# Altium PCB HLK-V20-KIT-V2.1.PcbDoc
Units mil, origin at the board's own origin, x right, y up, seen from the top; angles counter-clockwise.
Board outline 1181.1 x 1102.36 mil, 2 copper layers (Top Layer, Bottom Layer); 18 components, 58 nets, 96 pads, 45 vias.
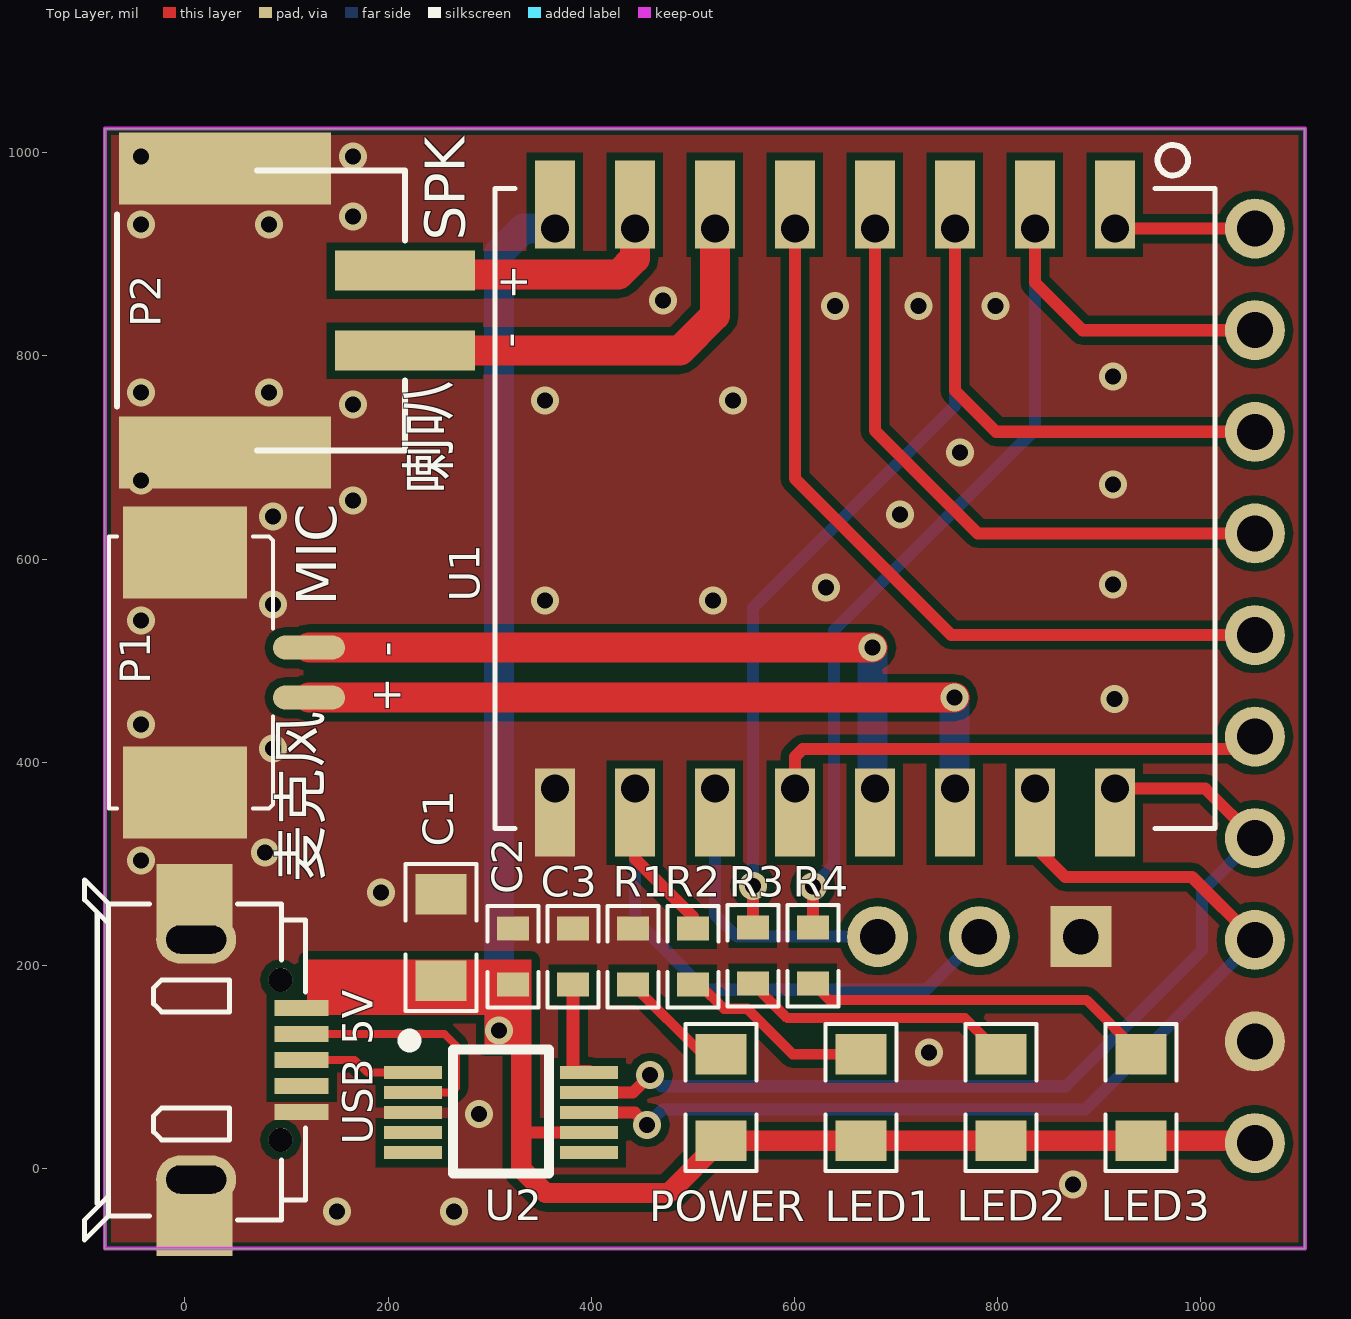
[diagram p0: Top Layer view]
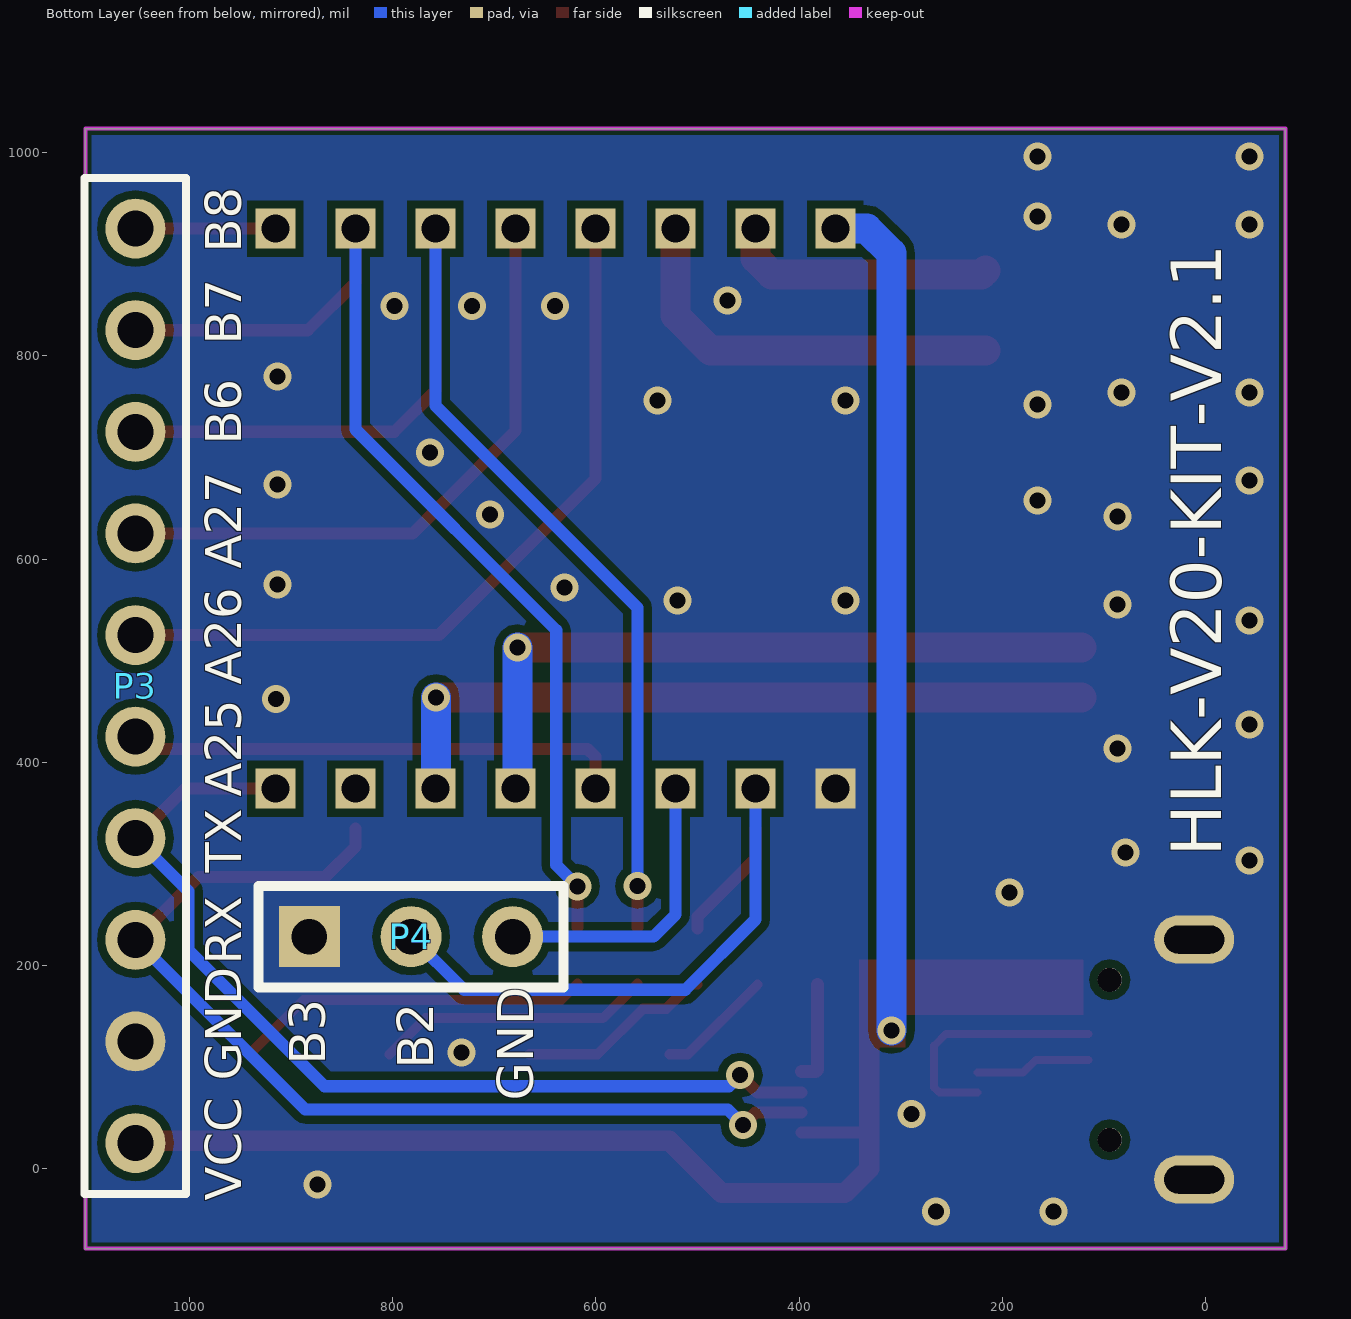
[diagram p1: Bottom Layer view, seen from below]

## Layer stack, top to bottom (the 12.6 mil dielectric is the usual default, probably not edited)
Top Layer: signal copper 1.4
Dielectric: dielectric 12.6, FR-4, Dk 4.8
Bottom Layer: signal copper 1.4

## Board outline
-78.74,-78.74 -78.74,1023.62 1102.36,1023.62 1102.36,-78.74

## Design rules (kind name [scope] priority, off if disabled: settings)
Clearance Clearance_1 [OnLayer('Keep-Out Layer')] p1: gap=3.94
Clearance [All] p2: gap=7.87
PlaneConnect [All] p1: planeconnectstyle=Direct reliefexpansion=20 reliefentries=4 reliefconductorwidth=10 reliefairgap=10
PolygonConnect [All] p1: connectstyle=Direct reliefconductorwidth=10 reliefentries=4 polygonreliefangle="90 Angle"
RoutingVias [All] p1: holewidth=15.75 width=27.56 viastyle="Through Hole" minholewidth=15.75 minwidth=27.56 maxholewidth=15.75 maxwidth=27.56
SilkscreenOverComponentPads SilkToSolderMaskClearance [IsPad] p1: minsilkscreentomaskgap=10
SolderMaskExpansion [All] p1: expansion=4
TestPointUsage FabricationTestPointUsage [All] p1: valid=0 allowmultiple=FALSE
Testpoint FabricationTestpoint [(IsPad And (OnTopLayer Or OnBottomLayer))] p1: side=3 testpointundercomponent=TRUE minsize=40 maxsize=100 preferedsize=60 minholesize=0 maxholesize=40 preferedholesize=32 testpointgrid=1 style=297 order=0123456789
Width [All] p1: maxlimit=196.85 minlimit=7.09 preferedwidth=10
22 further rules are at their usual default settings.

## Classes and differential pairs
component class HLK-V01-KIT-V1.0: C1 C2 LED1 LED2 LED3 P1 POWER R1 R2 R3 R4 R10 R11 "USB 5V"

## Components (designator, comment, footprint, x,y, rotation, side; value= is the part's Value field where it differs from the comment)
C1 "4.7UF" 0805R 251.97,270.04 r270 top
C2 "0.1UF" 0603 322.83,208.66 r270 top
C3 "0.1UF" 0603 381.89,208.66 r270 top
LED1 "LED2" 0805R 665.35,27.56 r90 top
LED2 "LED2" 0805R 803.15,27.56 r90 top
LED3 "LED3" 0805R 940.94,27.56 r90 top
P1 "1.25*2_SMT" 1.25-2P 122.05,488.19 r90 top locked
P2 "2.0*2_SMT" PH2.0-2P 216.54,805.12 r90 top
P3 "2.54*10" HDR1X10 1053.15,925.2 r270 bottom locked
P4 "2.54*3" SIP3 881.89,228.35 r180 bottom
POWER "LED" 0805R 527.56,27.56 r90 top
R1 "1K" 0603 440.94,208.66 r90 top
R2 "1K" 0603 500,208.66 r90 top
R3 "1K" 0603 559.06,209.66 r90 top (schematic designator R4)
R4 "1K" 0603 618.11,209.66 r90 top (schematic designator R10)
U1 "Comment" HLK-V20 915.35,964.57 r270 top
U2 "CH340E" MSOP-10 311.02,55.12 r270 top (schematic designator U1)
"USB 5V" "USB" usb 7.87,106.3 r270 top locked (schematic designator USB1)

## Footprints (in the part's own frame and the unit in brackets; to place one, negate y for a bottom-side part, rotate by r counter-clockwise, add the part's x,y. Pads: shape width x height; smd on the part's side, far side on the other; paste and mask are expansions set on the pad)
1.25-2P [mm]
  oval 0.6x1.8 smd: 1(0.625,0) 2(-0.625,0)
  rect 2.3x3.1 smd: 3(-3,3.1) 4(3,3.1)
  silkscreen extent -3.4,0.9 3.4,5
0603 [mm]
  rect 0.6x0.8 smd: 1(-0.7,0) 2(0.7,0)
  silkscreen extent -1.27,-0.64 1.27,0.64
0805R [mil]
  rect 40x50 smd: 1(0,0) 2(85,0)
  silkscreen extent -30,-35 115,35, body extent 4,-25 83,25, height 22
HDR1X10 [mm]
  round 1.5 hole 0.9: 1(0,0) 2(2.54,0) 3(5.08,0) 4(7.62,0) 5(10.16,0) 6(12.7,0) 7(15.24,0) 8(17.78,0) 9(20.32,0) 10(22.86,0)
  silkscreen extent -1.27,-1.27 24.13,1.27
HLK-V20 [mm]
  rect 1.4x1 smd: 1(0,0) 2(0,-2) 3(0,-4) 4(0,-6) 5(0,-8) 6(0,-10) 7(0,-12) 8(0,-14) 9(16,-14) 10(16,-12) 11(16,-10) 12(16,-8) 13(16,-6) 14(16,-4) 15(16,-2) 16(16,0)
  rect 1x1 hole 0.7: 1(1,0) 2(1,-2) 3(1,-4) 4(1,-6) 5(1,-8) 6(1,-10) 7(1,-12) 8(1,-14) 9(15,-14) 10(15,-12) 11(15,-10) 12(15,-8) 13(15,-6) 14(15,-4) 15(15,-2) 16(15,0)
  silkscreen extent -1.09,-15.5 16,2.5
MSOP-10 [mm]
  rect 0.33x1.45 smd: 1(-1,-2.2) 2(-0.5,-2.2) 3(0,-2.2) 4(0.5,-2.2) 5(1,-2.2) 6(1,2.2) 7(0.5,2.2) 8(0,2.2) 9(-0.5,2.2) 10(-1,2.2)
  silkscreen extent -1.95,-2.44 1.53,1.2
PH2.0-2P [mm]
  rect 1x3.5 smd: 1(0,0) 2(2,0)
  rect 1.8x5.3 smd: 3(4.55,4.5) 4(-2.55,4.5)
  silkscreen extent -2.5,0 4.5,7.2
SIP3 [mil]
  rect 60x60 hole 35: 1(0,0)
  round 60 hole 35: 2(100,0) 3(200,0)
  silkscreen extent -50,-50 250,50
usb [mm]
  oval 1.2x2 hole 0.7 slot 1.5 at 90 deg: 1(-3.028,0.081) 1(2.972,0.081)
  rect 0.4x1.35 smd: 1(1.28,2.719) 2(0.63,2.719) 3(-0.02,2.719) 4(-0.67,2.719) 5(-1.32,2.719)
  round 0.6 hole 0.6: 6(1.98,2.194) 9(-2.02,2.194)
  rect 1.8x1.9 smd: 7(3.98,0.044) 8(-4.02,0.044)
  silkscreen extent -4.52,-2.71 4.48,2.82

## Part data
C1 C2 C3: library part CAP, "Capacitor"
LED1 LED2 LED3: library part LED
P1: library part Component_1
R1 R2 R3 R4: library part RES1
"USB 5V": library part USB-B

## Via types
v1: diameter 27.56, hole 15.75, Top Layer to Bottom Layer, tented both sides, 45 vias

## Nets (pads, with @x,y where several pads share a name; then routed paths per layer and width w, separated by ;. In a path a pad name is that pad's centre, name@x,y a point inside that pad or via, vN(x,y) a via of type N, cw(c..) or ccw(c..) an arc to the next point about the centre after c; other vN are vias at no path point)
3.3V: 
5V: "USB 5V.5" C1.2 C2.2 LED1.1 LED2.1 LED3.1 P3.10 POWER.1 U1.8 U2.7 | length 1943.7
  Top Layer w10: 333,54 333,164
  Top Layer w12: 333,35.43 U2.7
  Top Layer w20: C2.2 331,172.94 331,0 355,-24 476,-24 POWER.1 LED1.1 LED2.1 LED3.1 1050.79,27.56 P3.10
  Bottom Layer w29.53: v1(309,136) 309,901 333.2,925.2 U1.8@364.17,925.2
ACE_N: 
ACE_P: 
CTS: U2.5
DM: "USB 5V.4" U2.2 | length 242.7
  Top Layer w7.87: 114.91,132.68 255.32,132.68 267,121 267,80 261.8,74.8 U2.2
DP: "USB 5V.3" U2.1 | length 114.7
  Top Layer w7.87: 114.91,107.09 166.91,107.09 179.51,94.49 U2.1
GND: "USB 5V.1" "USB 5V.7" "USB 5V.8" C1.1 C2.1 C3.1 P1.3 P1.4 P2.3 P2.4 P3.9 P4.1 R1.2 U1.9 U2.3
  other v1: 149.61,-42.22 265,-42 874.02,-15.75 289.32,54 732.28,114.17 192.91,271.65 -43.31,303.15 78.74,311.02 86.61,413.39 -43.31,437.01 915,462 -43.31,539.37 86.61,555.12 354.33,559.06 519.68,559.06 631,572 913.39,574.8 86.61,641.73 704,644 165.35,657.48 913.39,673.23 -43.31,677.17 763,705 165.35,751.97 354.33,755.91 539.37,755.91 -43.31,763.78 82.68,763.78 913.39,779.53 640,849 722,849 798,849 470.47,854.33 -43.31,929.13 82.68,929.13 165.35,937.01 -43.31,996.06 165.35,996.06
IO9: 
IO10: 
IO11: 
MIC0_N: 
MIC0_P: 
MIC+: P1.2 U1.14 | length 725.1
  Top Layer w29.53: P1.2 v1(757.29,463.58)
  Bottom Layer w29.53: v1(757.29,463.58) 757.29,374.6 U1.14@757.87,374.02
MIC-: P1.1 U1.13 | length 694.6
  Top Layer w29.53: P1.1 v1(676.93,512.8)
  Bottom Layer w29.53: v1(676.93,512.8) 676.93,376.22 U1.13@679.13,374.02
NetC3_2: C3.2 U2.10 | length 100.3
  Top Layer w12.99: C3.2 381.89,97.11 383.33,95.67 U2.10@397.64,95.67
NetCHRX_1: 
NetCHTX_1: 
NetLED1_2: LED1.2 R2.1 | length 193.7
  Top Layer w10: R2.1 506.9,181.1 530.59,157.41 553.45,157.41 598.31,112.56 LED1.2
NetLED2_2: LED2.2 R3.1 | length 272.9
  Top Layer w10: R3.1 593.03,148.13 767.58,148.13 LED2.2
NetLED3_2: LED3.2 R4.1 | length 351.6
  Top Layer w10: R4.1 634.21,166 887.5,166 LED3.2
NetON/OFF_2: 
NetP1_1: 
NetP1_2: 
NetP2_1: 
NetP2_2: 
NetPOWER_2: POWER.2 R1.1 | length 115
  Top Layer w10: R1.1 509.49,112.56 POWER.2
NetR3_1: 
NetR10_2: 
NetR12_1: 
NetRST_2: 
PA_N: 
PA_P: 
PWM0: 
RTS: U2.4
RX0_CH340E: 
RXD: 
SIO0: 
SIO1: 
SPK+: P2.2 U1.7 | length 263.9
  Top Layer w29.53: P2.2 220.39,880 427,880 442.91,895.91 U1.7@442.91,925.2
SPK-: P2.1 U1.6 | length 405
  Top Layer w29.53: P2.1 487.12,805.12 521.65,839.65 U1.6@521.65,925.2
TCK/IO4: 
TDI/IO7: 
TDO/IO6: 
TMS/IO5: 
TX0_CH340E: 
TXD: 
UART_RX: P3.8 U1.15 U2.8 | length 1071.6
  Top Layer w12: U2.8 442.88,55.12 v1(455,43) ; U1.15@836.61,334.65 836.61,316.93 866.54,287 917.32,287 ; 980.72,287 917.32,287 ; P3.8 991.35,287 917.32,287
  Bottom Layer w12: v1(455,43) 470.13,58.13 886.08,58.13 P3.8
UART_TX: P3.7 U1.16 U2.9 | length 965.6
  Top Layer w12: U2.9 440.8,74.8 v1(458,92) ; U1.16@915.35,374.02 1004.33,374.02 P3.7
  Bottom Layer w12: v1(458,92) 469,81 867,81 1001,215 1001,267.84 1001,273.05 P3.7 P3.7@1053.15,319.99
US_GPIO_B2: P4.2 R2.2 U1.10 | length 640.3
  Top Layer w12: U1.10@442.91,334.65 442.91,305.09 500,248 R2.2
  Bottom Layer w12: U1.10@442.91,374.02 442.91,245.09 512,176 729.54,176 P4.2
US_GPIO_B3: P4.3 U1.11 | length 293.2
  Bottom Layer w12: U1.11@521.65,374.02 521.65,250 543.31,228.35 P4.3
US_GPIO_B6: P3.3 R3.2 U1.3 | length 1241.9
  Top Layer w12: R3.2 v1(559.06,277.94) ; U1.3@757.87,925.2 757.87,765.75 798.43,725.2 P3.3
  Bottom Layer w12: v1(559.06,277.94) 559.06,552.06 757.87,750.87 U1.3@757.87,925.2
US_GPIO_B7: P3.2 R4.2 U1.2 | length 1067.6
  Top Layer w12: R4.2 v1(618.11,277.83) ; U1.2@836.61,925.2 836.61,872.05 883.46,825.2 P3.2
  Bottom Layer w12: v1(618.11,277.83) 639,298.72 639,530 836.61,727.61 U1.2@836.61,925.2
US_GPIO_B8: P3.1 U1.1 | length 137.8
  Top Layer w12: U1.1@915.35,925.2 P3.1
US_SPIM_CLK: P3.5 U1.5 | length 762.6
  Top Layer w12: U1.5@600.39,925.2 600.39,679.13 740.06,539.46 754.33,525.2 P3.5
US_SPIM_MISO: P3.6 U1.12 | length 499.4
  Top Layer w12: U1.12@600.39,374.02 600.39,405.39 608.13,413.13 1053.15,413.13 P3.6
US_SPIM_MOSI: P3.4 U1.4 | length 614.7
  Top Layer w12: U1.4@679.13,925.2 679.13,752.87 679.13,726.38 780.31,625.2 P3.4
VMIC: 
pads on no net: "USB 5V.2" "USB 5V.6" "USB 5V.9" U2.6

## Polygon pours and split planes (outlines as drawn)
GND on Top Layer "MidLayer1-No Net" (solid, remove dead copper, pour order 4): -78.74,-78.74 1102.36,-78.74 1102.36,1023.62 -78.74,1023.62
GND on Bottom Layer "MidLayer1-No Net" (solid, remove dead copper, pour order 6): -78.74,-78.74 1102.36,-78.74 1102.36,1023.62 -78.74,1023.62

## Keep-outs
Keep-Out Layer:
  the board outline again, w3.94

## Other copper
Top Layer:
  rectangle net 5V: 295,119 341,151
  rectangle net 5V: 120,151 341,206

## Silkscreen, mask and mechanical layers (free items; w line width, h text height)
Top Overlay:
  text "SPK" at 275.59,913.39 h39.37 r90
  text "+" at 311.02,889.76 h30 r270
  text "-" at 311.02,822.83 h30 r270
  text "喇叭" at 273,664 h70 r90
  text "MIC" at 149,554 h39.37 r90
  text "-" at 212.6,503.94 h30 r90
  text "+" at 212.6,448.82 h30 r90
  text "麦克风" at 147,282 h70 r90
Bottom Overlay:
  text "B8" at 948.82,901.57 h35.43 r270
  text "B7" at 948.82,811.02 h35.43 r270
  text "B6" at 948.82,712.6 h35.43 r270
  text "A27" at 948.82,590.55 h35.43 r270
  text "A26" at 948.82,476.38 h35.43 r270
  text "A25" at 948.82,366.14 h35.43 r270
  text "HLK-V20-KIT-V2.1" at -15.75,307.09 h50 r270
  text "TX" at 948.82,291.34 h35.43 r270
  text "RX" at 948.82,200.79 h35.43 r270
  text "B3" at 866.14,102.36 h35.43 r270
  text "B2" at 759.84,98.43 h35.43 r270
  text "GND" at 948.82,86.61 h35.43 r270
  text "GND" at 661.42,66.93 h35.43 r270
  text "VCC" at 948.82,-31.5 h35.43 r270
